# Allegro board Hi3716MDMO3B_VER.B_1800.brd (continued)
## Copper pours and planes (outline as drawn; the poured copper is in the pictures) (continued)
$4N23 on TOP (solid shape): 127.16,93.48 127.16,89.68 127.16,89.68 127.16,89.28 126.78,88.91 126.39,88.91 126.39,88.91 120.3,88.91 119.92,89.29 119.92,93.48 120.31,93.86 126.78,93.86
$4N24 on TOP (solid shape): 126.27,88.52 127.55,88.52 127.93,88.15 127.93,84.34 127.55,83.96 120.18,83.96 119.92,84.21 119.92,88.28 120.18,88.53 126.26,88.53
$17N126 on TOP (solid shape): 238.21,107.83 238.3,107.77 238.28,107.66 238.1,106.72 238.9,106.19 239.46,106.19 240.25,106.72 240.05,107.77 240.15,107.83 241.08,107.83 242.73,106.18 244.77,106.18 245.02,105.93 245.02,104.4 244.77,104.15 242.1,104.15 240.32,105.93 233.97,105.93 233.72,106.18 233.72,107.58 233.97,107.83
$17N128 on TOP (solid shape): 253.15,111.39 256.07,108.47 260.89,108.47 261.4,107.96 261.4,106.94 261.15,106.69 256.67,106.69 256.64,106.67 254.38,106.67 253.39,105.68 246.79,105.68 245.52,106.95 243.1,106.95 242.98,107.07 242.98,108.85 243.23,109.11 245.01,109.11 247.3,111.39 253.15,111.39
$19N8 on TOP (solid shape): 31.91,95.51 31.91,90.05 31.41,89.54 30.01,89.54 28.36,87.89 28.36,85.23 28.29,85.16 28.28,85.16 28.14,85.06 28.04,84.92 28.04,84.91 27.72,84.59 27.72,82.43 27.6,82.31 26.96,82.31 26.83,82.43 26.83,85.61 25.18,87.26 25.18,88.66 25.44,88.91 27.21,88.91 30.14,91.83 30.14,95.51 30.26,95.64 31.79,95.64
$19N10 on TOP (solid shape): 31.79,119.64 31.79,117.1 30.73,116.05 30.02,115.34 29.95,115.37 28,115.37 28,113.09 29.63,113.09 29.63,111.52 28.87,110.75 28.87,107.38 28.84,107.34 28.83,107.33 28.7,107.18 28.64,106.99 28.64,106.97 28.36,106.69 27.09,106.69 26.96,106.56 26.96,104.53 26.83,104.4 26.2,104.4 26.07,104.53 26.07,114.56 30.01,118.5 30.01,118.83 30.02,118.84 30.02,119.66 30.14,119.77 31.66,119.77
$19N37 on TOP (solid shape): 31.66,133.11 31.66,130.95 31.91,130.69 33.31,130.69 33.56,130.44 33.56,129.17 33.31,128.91 27.72,128.91 26.07,130.57 26.07,133.36 26.45,133.74 31.02,133.74
$19N38 on TOP (solid shape): 23.28,133.23 23.28,130.31 19.98,127.01 16.67,127.01 16.17,127.52 16.17,133.23 16.67,133.74 22.77,133.74
$19N39 on TOP (solid shape): 31.79,142.12 31.79,141.64 31.79,137.17 28.87,134.25 16.67,134.25 16.17,134.76 16.17,137.55 16.67,138.06 22.52,138.06 27.09,142.63 31.28,142.63
$19N61 on TOP (solid shape): 24.67,89.29 24.67,87.13 26.45,85.35 26.45,82.43 26.33,82.31 25.69,82.31 25.56,82.43 25.56,84.72 24.93,85.35 21.37,85.35 21.12,85.61 21.12,89.29 21.37,89.54 24.42,89.54
$19N64 on TOP (solid shape): 25.69,113.55 25.69,104.53 25.56,104.4 24.93,104.4 24.8,104.53 24.8,106.69 21.25,110.25 21.25,113.55 21.5,113.8 25.44,113.8

Small or netless copper shapes (teardrops, artwork), in the pictures only: 11 on TOP

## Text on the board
BOTTOM: HI3716MDMO3B_VER.A ARTWORK BOTTOM
Ref Des/Silkscreen Bottom: HI3716MDMO3B_VER.A SILKSCREEN BOTTOM
User.Comments: HI3716MDMO3B_VER.A SOLDMASK TOP | HI3716MDMO3B_VER.A SOLDMASK BOTTOM
TOP: HI3716MDMO3B_VER.A ARTWORK TOP | www.pcbb.com  The  PCB File share  QQ Group:562010407
Ref Des/Silkscreen Top: Hi3716MJTB VER.A | Hi3716MFPB VER.A | Hi3716MRSB VER.A | Hi3716MSMB VER.A | Hi3716MPWB VER.A | HI3716MDMO3B_VER.A SILKSCREEN TOP | HI3716MDMO3B VER.A | BAR CODE
DIMENSION: 2 | PLATED OVAL SLOT:120X40mil | PLATED OVAL SLOT:40x120mil | PLATED OVAL SLOT:40x135mil | 2XPlated OVAL hole:36X82mil | 2XPlated OVAL hole:36X105mil | 2XOBLONG VIA50X180MIL | 2XOBLONG VIA40X70MIL | 4XOBLONG VIA100X40MIL | 2-open window: 71x118mil | HI3716MDMO3B_VER.A DRILL CHART | 1--Gerber TOP | 2--Gerber BOTTOM
DISPLAY_BOTTOM: HI3716MDMO3B_VER.A PASTEMASK BOTTOM
DISPLAY_TOP: HI3716MDMO3B_VER.A PASTEMASK TOP
DEVICE_TYPE_BOTTOM: FIGURE | SIZE | 8.0 | 10.0 | 12.0 | 32.0 | 35.0 | 36.0 | 40.0 | 43.0 | 45.0 | 50.0 | 52.0 | 60.0 | 65.0 | 80.0 | 90.0 | 125.0 | 71.0 | 126.0 | 135.0 | 138.0 | 70.0x40.0 | 100.0x40.0 | 180.0x50.0 | DRILL CHART: TOP to BOTTOM | ALL UNITS ARE IN MILS | PLATED | NON-PLATED | QTY | 6043 | 14 | 184 | 36 | 8 | 127 | 102 | 2 | 32 | 16 | 4 | 3 | 6 | 240 | 23
